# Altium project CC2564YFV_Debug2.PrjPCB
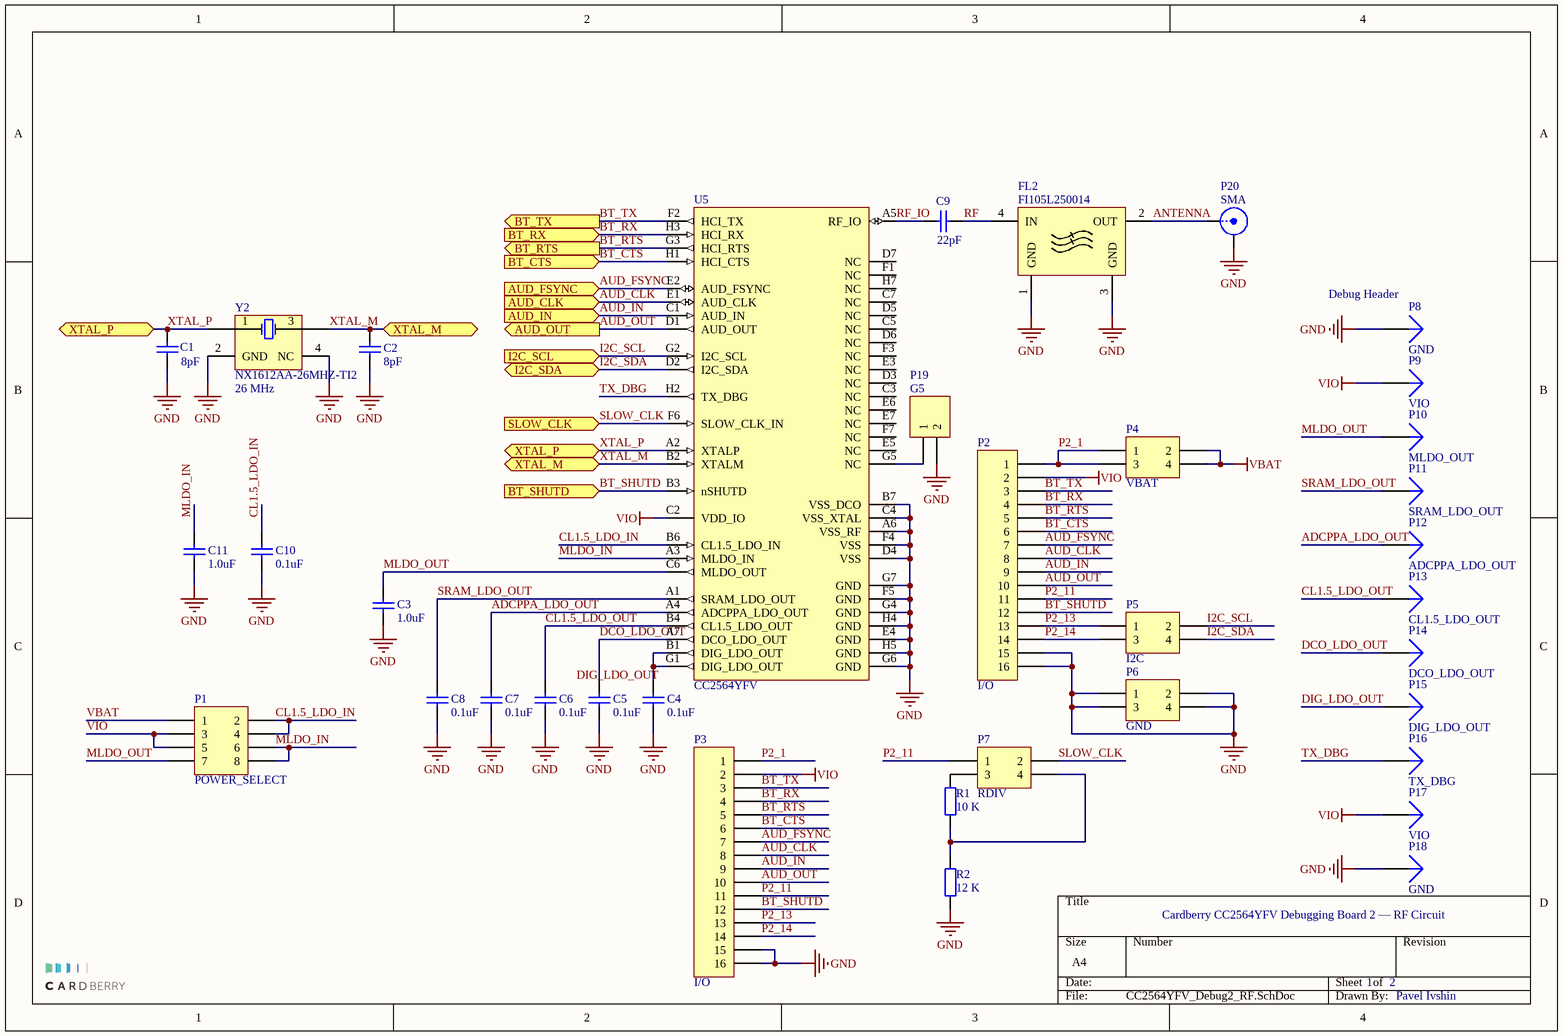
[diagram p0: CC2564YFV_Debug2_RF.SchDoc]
2 sheets, 42 parts. Net scope: flat (ports and power ports of the same name join across sheets).
Board file: CC2564YFV_Debug2.PcbDoc
Sheets:
  CC2564YFV_Debug2_RF.SchDoc
  CC2564YFV_Debug2_Add.SchDoc

## Sheet CC2564YFV_Debug2_RF.SchDoc: Cardberry CC2564YFV Debugging Board 2 — RF Circuit
size A4; DrawnBy: Pavel Ivshin; Engineer: Pavel Ivshin; Organization: Cardberry; Revision: 0; SheetNumber: 1; SheetTotal: 2

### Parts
C1  value 8pF  [0402]  (hidden comment: Cap Semi 8 pF)
C2  value 8pF  [0402]  (hidden comment: Cap Semi 8 pF)
C3  value 1.0uF  [0402]  (hidden comment: C1005X5R1A105K050BB)
C4  value 0.1uF  [0402]  (hidden comment: C1005X7R1H104M050BB)
C5  value 0.1uF  [0402]  (hidden comment: C1005X7R1H104M050BB)
C6  value 0.1uF  [0402]  (hidden comment: C1005X7R1H104M050BB)
C7  value 0.1uF  [0402]  (hidden comment: C1005X7R1H104M050BB)
C8  value 0.1uF  [0402]  (hidden comment: C1005X7R1H104M050BB)
C9  value 22pF  [1-0201]  (hidden comment: GRM0335C1E220JA01D)
C10  value 0.1uF  [0402]  (hidden comment: C1005X7R1H104M050BB)
C11  value 1.0uF  [0402]  (hidden comment: C1005X5R1A105K050BB)
FL2  FI105L250014  [FL105_Electrodes]
P1  POWER_SELECT  [HDR2X4]
P2  I/O  [HDR1X16]
P3  I/O  [HDR1X16]
P4  VBAT  [HDR2X2]
P5  I2C  [HDR2X2]
P6  GND  [HDR2X2]
P7  RDIV  [HDR2X2]
P8  GND  [PIN1]
P9  VIO  [PIN1]
P10  MLDO_OUT  [PIN1]
P11  SRAM_LDO_OUT  [PIN1]
P12  ADCPPA_LDO_OUT  [PIN1]
P13  CL1.5_LDO_OUT  [PIN1]
P14  DCO_LDO_OUT  [PIN1]
P15  DIG_LDO_OUT  [PIN1]
P16  TX_DBG  [PIN1]
P17  VIO  [PIN1]
P18  GND  [PIN1]
P19  G5  [HDR1X2]
P20  SMA  [SMA]
R1  value 10 K  [3-0603]  (hidden comment: Res Chip 10 K)
R2  value 12 K  [3-0603]  (hidden comment: Res Chip 12 K)
U5  CC2564YFV  [YFV (R-XBGA-N54)]
Y2  NX1612AA-26MHZ-TI2  value 26 MHz  [XTAL_QUAD_1.6x1.2mm]

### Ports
AUD_CLK (in), AUD_FSYNC (in), AUD_IN (in), AUD_OUT (out), BT_CTS (in), BT_RTS (out), BT_RX (in), BT_SHUTD (in), BT_TX (out), I2C_SCL (in), I2C_SDA (bidir), SLOW_CLK (in), XTAL_M (bidir), XTAL_P (bidir)

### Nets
GND: C1.1 C2.1 C3.1 C4.1 C5.1 C6.1 C7.1 C8.1 C10.1 C11.1 FL2.1(GND) FL2.3(GND) P2.15 P2.16 P3.15 P3.16 P6.1 P6.2 P6.3 P6.4 P8.1 P18.1 P19.2 P20.2(Y) R2.1 U5.A6(VSS_RF) U5.B7(VSS_DCO) U5.C4(VSS_XTAL) U5.D4(VSS) U5.E4(GND) U5.F4(VSS) U5.F5(GND) U5.G4(GND) U5.G6(GND) U5.G7(GND) U5.H4(GND) U5.H5(GND) Y2.2(GND) Y2.4(NC)
VBAT: P1.1 P4.2 P4.4
VIO: P1.3 P1.5 P2.2 P3.2 P9.1 P17.1 U5.C2(VDD_IO)
ADCPPA_LDO_OUT: C7.2 P12.1 U5.A4(ADCPPA_LDO_OUT)
ANTENNA: FL2.2(OUT) P20.1(X)
AUD_CLK: P2.8 P3.8 U5.E1(AUD_CLK) ; port AUD_CLK
AUD_FSYNC: P2.7 P3.7 U5.E2(AUD_FSYNC) ; port AUD_FSYNC
AUD_IN: P2.9 P3.9 U5.C1(AUD_IN) ; port AUD_IN
AUD_OUT: P2.10 P3.10 U5.D1(AUD_OUT) ; port AUD_OUT
BT_CTS: P2.6 P3.6 U5.H1(HCI_CTS) ; port BT_CTS
BT_RTS: P2.5 P3.5 U5.G3(HCI_RTS) ; port BT_RTS
BT_RX: P2.4 P3.4 U5.H3(HCI_RX) ; port BT_RX
BT_SHUTD: P2.12 P3.12 U5.B3(nSHUTD) ; port BT_SHUTD
BT_TX: P2.3 P3.3 U5.F2(HCI_TX) ; port BT_TX
CL1.5_LDO_IN: C10.2 P1.2 P1.4 U5.B6(CL1.5_LDO_IN)
CL1.5_LDO_OUT: C6.2 P13.1 U5.B4(CL1.5_LDO_OUT)
DCO_LDO_OUT: C5.2 P14.1 U5.A7(DCO_LDO_OUT)
DIG_LDO_OUT: C4.2 P15.1 U5.B1(DIG_LDO_OUT) U5.G1(DIG_LDO_OUT)
I2C_SCL: P5.2 U5.G2(I2C_SCL) ; port I2C_SCL
I2C_SDA: P5.4 U5.D2(I2C_SDA) ; port I2C_SDA
MLDO_IN: C11.2 P1.6 P1.8 U5.A3(MLDO_IN)
MLDO_OUT: C3.2 P1.7 P10.1 U5.C6(MLDO_OUT)
P2_1: P2.1 P3.1 P4.1 P4.3
P2_11: P2.11 P3.11 P7.1
P2_13: P2.13 P3.13 P5.1
P2_14: P2.14 P3.14 P5.3
RF: C9.2 FL2.4(IN)
RF_IO: C9.1 U5.A5(RF_IO)
SLOW_CLK: P7.2 U5.F6(SLOW_CLK_IN) ; port SLOW_CLK
SRAM_LDO_OUT: C8.2 P11.1 U5.A1(SRAM_LDO_OUT)
TX_DBG: P16.1 U5.H2(TX_DBG)
XTAL_M: C2.2 U5.B2(XTALM) Y2.3(OSC2) ; port XTAL_M
XTAL_P: C1.2 U5.A2(XTALP) Y2.1(OSC1) ; port XTAL_P
NetP7_3: P7.3 R1.2
NetP7_4: P7.4 R1.1 R2.2
NetP19_1: P19.1 U5.G5(NC)

Not connected (* = marked no-connect by the designer): U5 C3(NC) C5(NC) C7(NC) D3(NC) D5(NC) D6(NC) D7(NC) E3(NC) E5(NC) E6(NC) E7(NC) F1(NC) F3(NC) F7(NC) H7(NC)

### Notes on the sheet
- (near P8) Debug Header

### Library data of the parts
C1 C2 = Cap Semi 8 pF: Chip Capacitor, 8 pF
C3 C11 = C1005X5R1A105K050BB: 1.0 uF/10 V 0402
C4-C8 C10 = C1005X7R1H104M050BB: 0.1 uF/50 V 0402
C9 = GRM0335C1E220JA01D: 22 pF/25 V 0201
FL2 = FI105L250014: 2.4 GHz Low Pass Filter
P1 = Header 4X2: Header, 4-Pin, Dual row
P2 P3 = Header 16: Header, 16-Pin
P4-P7 = Header 2X2: Header, 2-Pin, Dual row
P8-P18 = Plug
P19 = Header 2: Header, 2-Pin
P20 = SMA: SMA Generic Connector
R1 = Res Chip 10 K: Chip Resistor, 10 K
R2 = Res Chip 12 K: Chip Resistor, 12 K
U5 = CC2564YFV: CC2564, 54-balls DSBGA
Y2 = NX1612AA-26MHZ-TI2: Crystal Oscillator 26 MHz

## Sheet CC2564YFV_Debug2_Add.SchDoc: Cardberry CC2564YFV Debugging Board 2 — Additional Circuits
size A4; DrawnBy: Pavel Ivshin; Engineer: Pavel Ivshin; Organization: Cardberry; Revision: 0; SheetNumber: 2; SheetTotal: 2
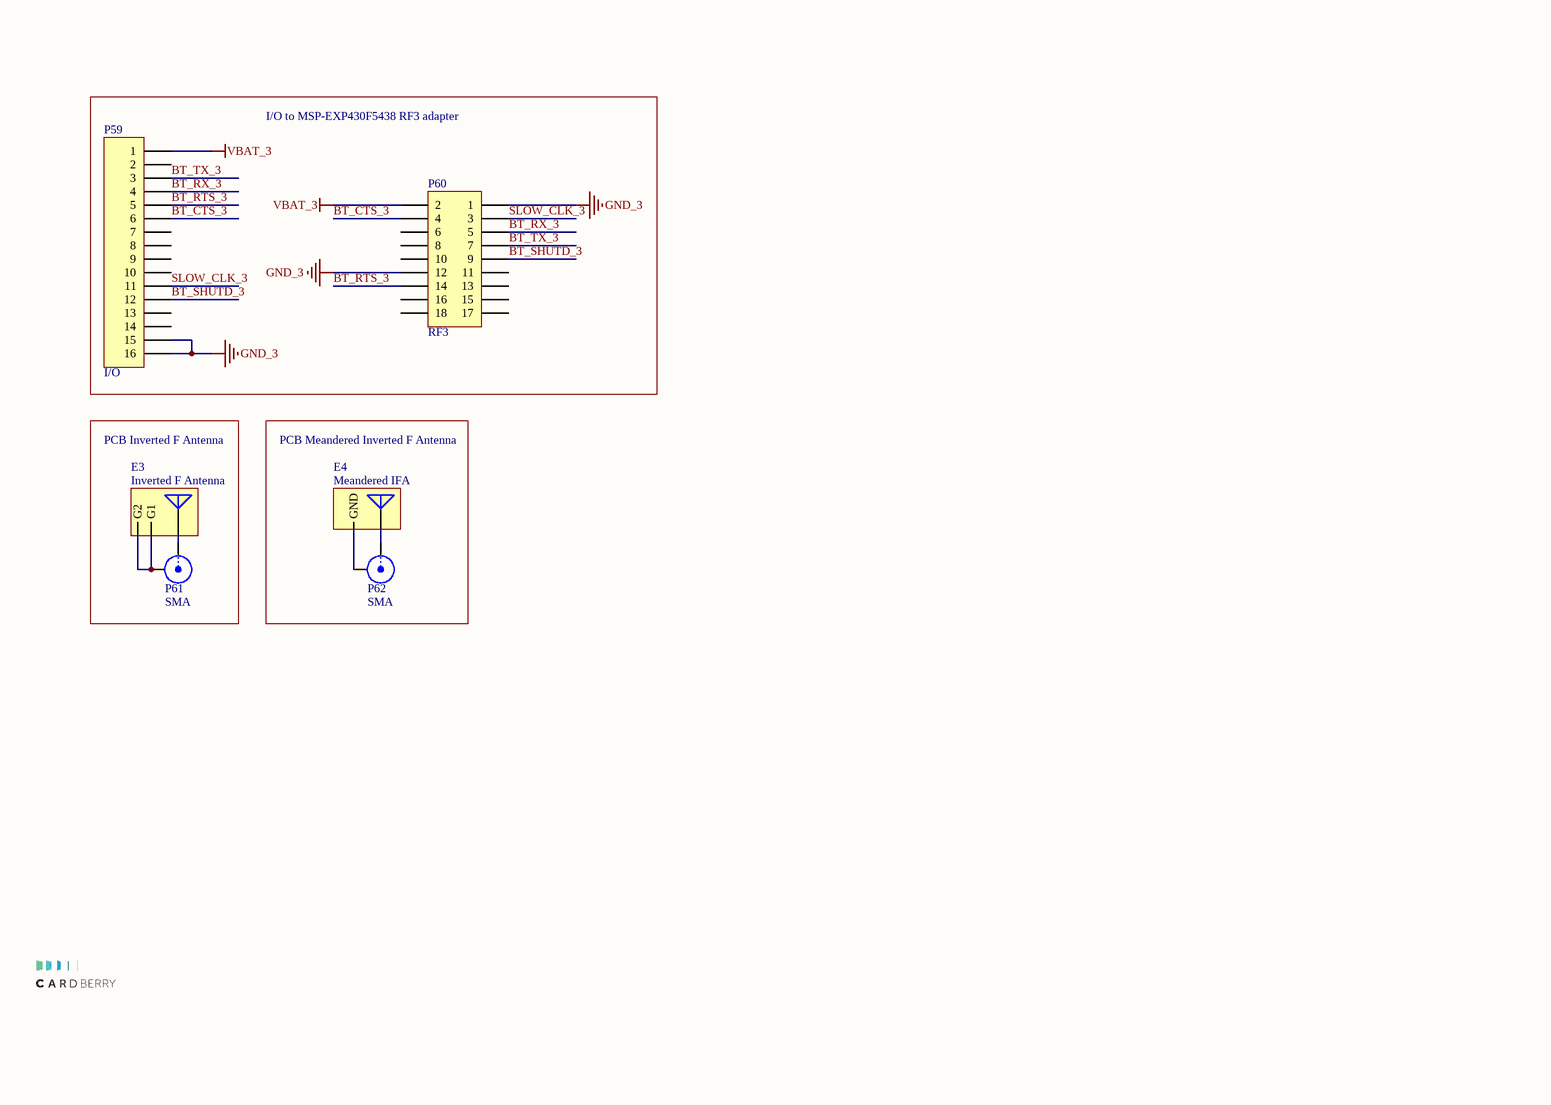
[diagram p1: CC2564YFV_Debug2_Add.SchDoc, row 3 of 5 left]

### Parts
E3  Inverted F Antenna  [Inverted_F_Antenna]
E4  Meandered IFA  [Meandered_IFA]  (no BOM)
P59  I/O  [HDR1X16]
P60  RF3  [HDR2X9]
P61  SMA  [SMA]
P62  SMA  [SMA]

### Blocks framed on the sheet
I/O to MSP-EXP430F5438 RF3 adapter: P59 P60
PCB Inverted F Antenna: E3 P61
PCB Meandered Inverted F Antenna: E4 P62

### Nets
GND_3: P59.15 P59.16 P60.1 P60.12
VBAT_3: P59.1 P60.2
BT_CTS_3: P59.6 P60.4
BT_RTS_3: P59.5 P60.14
BT_RX_3: P59.4 P60.5
BT_SHUTD_3: P59.12 P60.9
BT_TX_3: P59.3 P60.7
SLOW_CLK_3: P59.11 P60.3
NetE3_1: E3.1(FEED) P61.1(X)
NetE3_2: E3.2(G1) E3.3(G2) P61.2(Y)
NetE4_1: E4.1(FEED) P62.1(X)
NetE4_2: E4.2(GND) P62.2(Y)

Not connected (* = marked no-connect by the designer): P59 2 7 8 9 10 13 14; P60 6 8 10 11 13 15 16 17 18

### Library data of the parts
E3 = Inverted F Antenna: Inverted F Antenna (Design Note DN0007; SWRU120B)
E4 = Meandered IFA: Meandered Inverted F Antenna (Application Note AN043; SWRA117D)
P59 = Header 16: Header, 16-Pin
P60 = Header 9X2: Header, 9-Pin, Dual row
P61 P62 = SMA: SMA Generic Connector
